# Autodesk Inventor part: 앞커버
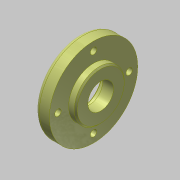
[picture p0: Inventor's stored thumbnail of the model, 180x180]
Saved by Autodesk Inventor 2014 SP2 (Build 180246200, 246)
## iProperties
Created: 2015-12
Part Number: 앞커버
Document SubType Name: Modeling
Designer: mdu
Density: 2.71 g/cm^3
Material: 알루미늄 6061
Mass: 70.9292 g
Surface Area: 93.9296 cm^2
Volume: 26.1731 cm^3
Appearance: 널링 45
Author: mdu
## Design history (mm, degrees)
sketch "스케치1"
  geometry: L1 (-7.5, 0)-(7.5, 0); L2 (-7.5, 0)-(-7.5, 31); L3 (-7.5, 31)-(2.5, 31); L4 (2.5, 31)-(2.5, 17.5); L5 (2.5, 17.5)-(7.5, 17.5); L6 (7.5, 17.5)-(7.5, 0); 2 further points
  constraints: 12 end point, 3 perpendicular, 1 coincident, 1 horizontal, 1 midpoint, 1 parallel
  dimensions: "d0" = 15 distance of L1.start L1.end; "d1" = 62 diameter of L3 L1; "d2" = 35 diameter of L5 L1; "d5" = 10 distance of L2.end L3.end
revolve "회전1" sketch "스케치1" stored, may be unused: angle "d6" = 90 deg
sketch "스케치2" dims "d42" = 50
  geometry: 3 further points
  constraints: 2 vertical alignment, 1 coincident, 2 other
hole "구멍1" sketch "스케치2" at (0, 25) diameter "d8" = 4.5; stored, may be unused: countersink angle "d12" = 90 deg, drill point angle "d14" = 118 deg; dims "d9" = 6, "d10" = 8, "d11" = 4.4, "d13" = 8
hole "구멍2" diameter "d20" = 18; stored, may be unused: countersink angle "d24" = 90 deg, drill point angle "d26" = 0 deg; dims "d18" = 10, "d19" = 10, "d21" = 6, "d22" = 8, "d23" = 4.4, "d25" = 8
hole "구멍3" diameter "d34" = 30; stored, may be unused: countersink angle "d38" = 90 deg, drill point angle "d40" = 0 deg; dims "d32" = 10, "d33" = 10, "d35" = 6, "d36" = 4, "d37" = 2, "d39" = 7.3
fillet "모깎기1" dims "d27" = 3, "d41" = 0.3
chamfer "모따기1" distance "d29" = 1; stored, may be unused: second distance "d30" = 2, angle "d31" = 45 deg
node "솔리드1"
pattern_circular "원형 패턴1" dims angle "d16" = 360 deg
